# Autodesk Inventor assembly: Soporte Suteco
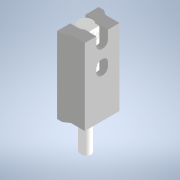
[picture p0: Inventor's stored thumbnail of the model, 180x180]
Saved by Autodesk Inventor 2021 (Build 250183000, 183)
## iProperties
Created: 2021-03
Part Number: Soporte Suteco
Document SubType Name: Assembly
Designer: ATOUZA
Author: ATOUZA
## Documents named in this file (3)
- D:\01 Paralaia\Grupos de Traballo\GT Maquetas\CAD 3D\E_AlimentaciónV1\Soportes Reed DM9B\Soporte Suteco.iam
- D:\01 Paralaia\Grupos de Traballo\GT Maquetas\CAD 3D\E_AlimentaciónV1\Soportes Reed DM9B\D-M9B.ipt
- D:\01 Paralaia\Grupos de Traballo\GT Maquetas\CAD 3D\E_AlimentaciónV1\Soportes Reed DM9B\Soporte Suteco.ipt
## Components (2 placed, 2 different names)
1. D-M9B:1
2. Soporte Suteco:1
